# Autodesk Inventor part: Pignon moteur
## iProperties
Author: Philippe
Created: 2002-01
Part Number: Pignon moteur
Material: Par défaut
Document SubType Name: Modélisation
Designer: Philippe
Control State: 0
Master: False
Checked Out: False
PropertySet Name: Design Tracking Control
Shininess: 27.0
Angle Display Precision: 2
Document Length Units: 11269
Document Angle Units: 11283
Document Time Units: 11279
Document Mass Units: 11290
Document Length Units Precision: 3
Document Angle Units Precision: 2
Compacted: False
PropertySet Name: _Private Model Information
Density: 0.0
Volumn: 0.0
Area: 0.0
PropertySet Name: Model Information
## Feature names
1. Extrusion1
2. Extrusion2
3. Réseau circulaire1 [Circular Pattern]
